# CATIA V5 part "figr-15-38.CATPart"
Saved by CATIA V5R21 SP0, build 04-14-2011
Part number: Part1
Bounding box of the stored display mesh (mm): x -63.331 to 99.803, y -39.139 to 39.139, z 0 to 68.615
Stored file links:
  D:\CATIA V5R21 E-RESOURCES\CATIA-V5R21\catia-v5r21-prt\c15-catia-v5r20-prt\c15-catia-v5r21-figr-15-38.CATPart
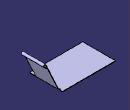
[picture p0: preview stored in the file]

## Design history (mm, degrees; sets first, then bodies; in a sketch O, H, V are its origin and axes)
SheetMetalParameters1: Thickness 1, BendRadius 2, KFactor 0.400515 {= log(min(100,max(20*SheetMetalParameters1.BendRadius,SheetMetalParameters1.Thickness)/SheetMetalParameters1.Thickness))/log(100)/2}, ReliefRadialLength 1, ReliefAxialLength 2, MinimumBendRadius 0
Body1 (main body)
  Sketch1 on xy-plane, origin (0, 0, 0), H (1, 0, 0), V (0, 1, 0)
    line L1 (-63.3311, 39.1393) -> (63.3311, 39.1393)
    line L2 (63.3311, 39.1393) -> (63.3311, -39.1393)
    line L3 (63.3311, -39.1393) -> (-63.3311, -39.1393)
    line L4 (-63.3311, -39.1393) -> (-63.3311, 39.1393)
    horizontal: L1 H, L3 H
    vertical: L2 V, L4 V
    symmetry: L4 L2 V, L1 L3 H
  Wall1: Thickness 1, Profile Sketch1
  d_NewWallOnEdge1: NewWallOnEdge_Edge edge [face of Wall1 | face of Wall1], NewWallOnEdge_Length 67, NewWallOnEdge_HeightLimitOffset 0, NewWallOnEdge_WidthOffset1 -16, NewWallOnEdge_WidthOffset2 -9, NewWallOnEdge_Angle 115, NewWallOnEdge_BendRadiusValue 2 {= SheetMetalParameters1.BendRadius}, NewWallOnEdge_BendTable SheetMetalParameters1, KFacteur 0.400515 {= log(min(100,max(20*d_NewWallOnEdge1.Radius,SheetMetalParameters1.Thickness)/SheetMetalParameters1.Thickness))/log(100)/2}
  Flange1: Angle 22.6199 {= 2*atan(Flange1.Radius/Flange1.Length)}, Length 10, Radius 2, KFacteur 0.400515 {= log(min(100,max(20*Flange1.Radius,SheetMetalParameters1.Thickness)/SheetMetalParameters1.Thickness))/log(100)/2}, Guide edge [face of d_NewWallOnEdge1 | face of d_NewWallOnEdge1]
